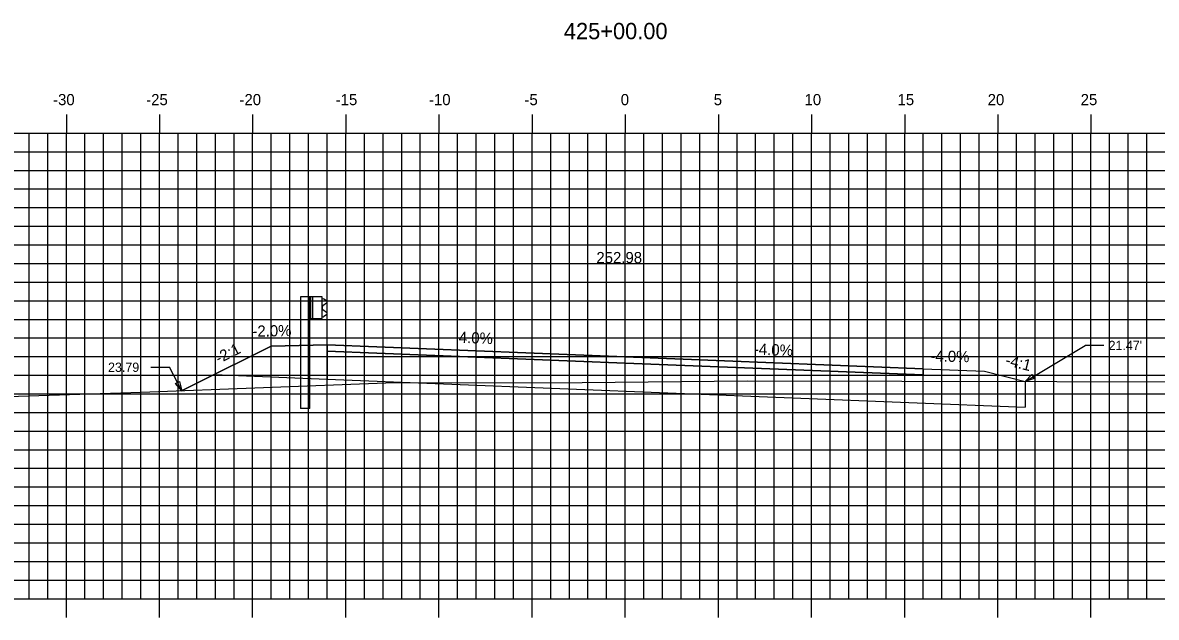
# Model space of a CAD drawing. Extents: x 1160718 to 1173142, y 616002 to 617630.
# Drawn here: x 1170373.6 to 1170434.4, y 616656.9 to 616688.9 of the extents above; entities that cross this region are included whole.
import ezdxf

# ---------------------------------------------------------------- set-up
doc = ezdxf.new("R2010")
doc.units = 0
for name, color, linetype in [('ANNOTATION', 7, 'Continuous'), ('D_Guardrail_Beam_Lt', 7, 'Continuous'), ('D_Roadway_Centerline', 7, 'Continuous'), ('D_Roadway_Centerline_Text', 7, 'Continuous'), ('D_Roadway_Edge_Shoulder', 7, 'Continuous'), ('D_Roadway_Edge_TW', 7, 'Continuous'), ('D_Roadway_Pavement', 7, 'Continuous'), ('D_Roadway_SlopeLines', 7, 'Continuous'), ('D_Roadway_SubGrade', 7, 'Continuous'), ('H_V ANNOTATION', 7, 'Continuous'), ('MAJOR', 7, 'Continuous'), ('MINOR', 7, 'Continuous'), ('S_Roadway_Centerline', 7, 'Continuous'), ('SHADING', 7, 'Continuous')]:
    doc.layers.add(name, color=color, linetype=linetype)

msp = doc.modelspace()

# ---------------------------------------------------------------- linework, layer by layer
at = {"layer": 'ANNOTATION'}
for p, q in [((1170427.372, 616669.597), (1170430.601, 616671.525)), ((1170431.601, 616671.525), (1170430.601, 616671.525)), ((1170380.439, 616670.355), (1170381.439, 616670.355)), ((1170382.112, 616669.095), (1170381.439, 616670.355)), ((1170421.907, 616670.273), (1170425.193, 616670.142))]:
    msp.add_line(p, q, dxfattribs=at)
for points in [[(1170427.865, 616669.746), (1170427.372, 616669.597), (1170427.737, 616669.961)], [(1170381.986, 616669.595), (1170382.112, 616669.095), (1170381.766, 616669.477)]]:
    msp.add_lwpolyline(points, close=True, dxfattribs=at)
at = {"layer": 'D_Guardrail_Beam_Lt'}
for p, q in [((1170388.48, 616674.136), (1170388.48, 616668.136)), ((1170388.951, 616674.136), (1170388.48, 616674.136)), ((1170389.638, 616674.136), (1170388.951, 616674.136)), ((1170388.951, 616674.136), (1170388.951, 616672.97)), ((1170389.013, 616674.136), (1170389.013, 616672.97)), ((1170389.117, 616674.136), (1170389.117, 616672.97)), ((1170389.638, 616672.97), (1170389.638, 616674.136)), ((1170389.638, 616674.053), (1170389.712, 616674.038)), ((1170389.728, 616674.032), (1170389.872, 616673.932)), ((1170389.643, 616673.588), (1170389.643, 616673.518)), ((1170389.872, 616673.789), (1170389.676, 616673.653)), ((1170389.676, 616673.454), (1170389.872, 616673.317)), ((1170388.951, 616672.97), (1170389.638, 616672.97)), ((1170388.971, 616668.136), (1170388.971, 616672.97)), ((1170389.712, 616673.068), (1170389.638, 616673.053)), ((1170389.872, 616673.174), (1170389.728, 616673.074)), ((1170388.971, 616668.136), (1170388.48, 616668.136))]:
    msp.add_line(p, q, dxfattribs=at)
for centre, major_axis, start_param, end_param in [((1170389.704, 616673.998), (0.0417, 0), 0.959931, 1.376053), ((1170389.721, 616673.588), (-0.0789, 0), 5.323254, 6.283185), ((1170389.721, 616673.518), (-0.0789, 0), 6.283185, 7.243116), ((1170389.821, 616673.86), (0.0877, 0), 5.323254, 7.243116), ((1170389.704, 616673.108), (0.0417, 0), 4.907132, 5.323254), ((1170389.821, 616673.246), (0.0877, 0), 5.323254, 7.243116)]:
    msp.add_ellipse(centre, major_axis=major_axis, ratio=0.995501, start_param=start_param, end_param=end_param, dxfattribs=at)
at = {"layer": 'D_Roadway_Centerline'}
for points in [[(1170382.083, 616669.081), (1170382.919, 616669.499), (1170386.907, 616671.493), (1170389.907, 616671.553), (1170405.907, 616670.913), (1170421.907, 616670.273)], [(1170425.193, 616670.142), (1170427.372, 616669.597)]]:
    msp.add_lwpolyline(points, dxfattribs=at)
at = {"layer": 'D_Roadway_Edge_Shoulder'}
for points in [[(1170389.907, 616671.553), (1170389.907, 616671.22)], [(1170421.907, 616670.273), (1170421.907, 616669.94)]]:
    msp.add_lwpolyline(points, dxfattribs=at)
at = {"layer": 'D_Roadway_Edge_TW'}
msp.add_lwpolyline([(1170421.907, 616669.94), (1170421.907, 616670.273), (1170405.907, 616670.913), (1170389.907, 616671.553), (1170389.907, 616671.22), (1170405.907, 616670.58)], close=True, dxfattribs=at)
at = {"layer": 'D_Roadway_Pavement'}
msp.add_lwpolyline([(1170421.907, 616669.94), (1170421.907, 616669.94), (1170405.907, 616670.58), (1170389.907, 616671.22), (1170389.907, 616671.22), (1170405.907, 616670.58)], close=True, dxfattribs=at)
for points in [[(1170389.907, 616671.22), (1170389.907, 616671.22)], [(1170389.907, 616671.22), (1170389.907, 616671.22)], [(1170421.907, 616669.94), (1170421.907, 616669.94)], [(1170421.907, 616669.94), (1170421.907, 616669.94)]]:
    msp.add_lwpolyline(points, dxfattribs=at)
at = {"layer": 'D_Roadway_SlopeLines'}
for points in [[(1170386.907, 616671.493), (1170382.083, 616669.081)], [(1170425.193, 616670.142), (1170427.372, 616669.597)]]:
    msp.add_lwpolyline(points, dxfattribs=at)
at = {"layer": 'D_Roadway_SubGrade'}
for p, q in [((1170389.907, 616671.553), (1170386.907, 616671.493)), ((1170389.907, 616669.72), (1170389.907, 616671.553)), ((1170386.907, 616671.493), (1170382.919, 616669.499)), ((1170405.907, 616670.58), (1170389.907, 616671.22)), ((1170389.907, 616671.22), (1170389.907, 616669.72)), ((1170421.907, 616669.94), (1170405.907, 616670.58)), ((1170421.907, 616668.44), (1170421.907, 616670.273)), ((1170421.907, 616668.44), (1170421.907, 616669.94)), ((1170425.193, 616670.142), (1170427.372, 616669.597)), ((1170427.372, 616669.597), (1170427.372, 616668.221))]:
    msp.add_line(p, q, dxfattribs=at)
at = {"layer": 'MAJOR'}
for p, q in [((1170375.907, 616683.93), (1170375.907, 616682.928)), ((1170380.907, 616683.93), (1170380.907, 616682.928)), ((1170385.907, 616683.93), (1170385.907, 616682.928)), ((1170390.907, 616683.93), (1170390.907, 616682.928)), ((1170395.907, 616683.93), (1170395.907, 616682.928)), ((1170400.907, 616683.93), (1170400.907, 616682.928)), ((1170405.907, 616683.93), (1170405.907, 616682.928)), ((1170410.907, 616683.93), (1170410.907, 616682.928)), ((1170415.907, 616683.93), (1170415.907, 616682.928)), ((1170420.907, 616683.93), (1170420.907, 616682.928)), ((1170425.907, 616683.93), (1170425.907, 616682.928)), ((1170430.907, 616683.93), (1170430.907, 616682.928)), ((1170335.907, 616682.928), (1170475.907, 616682.928)), ((1170335.907, 616682.928), (1170475.907, 616682.928)), ((1170375.907, 616657.928), (1170375.907, 616682.928)), ((1170380.907, 616657.928), (1170380.907, 616682.928)), ((1170385.907, 616657.928), (1170385.907, 616682.928)), ((1170390.907, 616657.928), (1170390.907, 616682.928)), ((1170395.907, 616657.928), (1170395.907, 616682.928)), ((1170400.907, 616657.928), (1170400.907, 616682.928)), ((1170405.907, 616657.928), (1170405.907, 616682.928)), ((1170410.907, 616657.928), (1170410.907, 616682.928)), ((1170415.907, 616657.928), (1170415.907, 616682.928)), ((1170420.907, 616657.928), (1170420.907, 616682.928)), ((1170425.907, 616657.928), (1170425.907, 616682.928)), ((1170430.907, 616657.928), (1170430.907, 616682.928)), ((1170335.907, 616677.928), (1170475.907, 616677.928)), ((1170335.907, 616672.928), (1170475.907, 616672.928)), ((1170335.907, 616667.928), (1170475.907, 616667.928)), ((1170335.907, 616662.928), (1170475.907, 616662.928)), ((1170335.907, 616657.928), (1170475.907, 616657.928)), ((1170335.907, 616657.928), (1170475.907, 616657.928)), ((1170375.907, 616656.926), (1170375.907, 616657.928)), ((1170380.907, 616656.926), (1170380.907, 616657.928)), ((1170385.907, 616656.926), (1170385.907, 616657.928)), ((1170390.907, 616656.926), (1170390.907, 616657.928)), ((1170395.907, 616656.926), (1170395.907, 616657.928)), ((1170400.907, 616656.926), (1170400.907, 616657.928)), ((1170405.907, 616656.926), (1170405.907, 616657.928)), ((1170410.907, 616656.926), (1170410.907, 616657.928)), ((1170415.907, 616656.926), (1170415.907, 616657.928)), ((1170420.907, 616656.926), (1170420.907, 616657.928)), ((1170425.907, 616656.926), (1170425.907, 616657.928)), ((1170430.907, 616656.926), (1170430.907, 616657.928))]:
    msp.add_line(p, q, dxfattribs=at)
at = {"layer": 'MINOR'}
for p, q in [((1170373.907, 616657.928), (1170373.907, 616682.928)), ((1170374.907, 616657.928), (1170374.907, 616682.928)), ((1170376.907, 616657.928), (1170376.907, 616682.928)), ((1170377.907, 616657.928), (1170377.907, 616682.928)), ((1170378.907, 616657.928), (1170378.907, 616682.928)), ((1170379.907, 616657.928), (1170379.907, 616682.928)), ((1170381.907, 616657.928), (1170381.907, 616682.928)), ((1170382.907, 616657.928), (1170382.907, 616682.928)), ((1170383.907, 616657.928), (1170383.907, 616682.928)), ((1170384.907, 616657.928), (1170384.907, 616682.928)), ((1170386.907, 616657.928), (1170386.907, 616682.928)), ((1170387.907, 616657.928), (1170387.907, 616682.928)), ((1170388.907, 616657.928), (1170388.907, 616682.928)), ((1170389.907, 616657.928), (1170389.907, 616682.928)), ((1170391.907, 616657.928), (1170391.907, 616682.928)), ((1170392.907, 616657.928), (1170392.907, 616682.928)), ((1170393.907, 616657.928), (1170393.907, 616682.928)), ((1170394.907, 616657.928), (1170394.907, 616682.928)), ((1170396.907, 616657.928), (1170396.907, 616682.928)), ((1170397.907, 616657.928), (1170397.907, 616682.928)), ((1170398.907, 616657.928), (1170398.907, 616682.928)), ((1170399.907, 616657.928), (1170399.907, 616682.928)), ((1170401.907, 616657.928), (1170401.907, 616682.928)), ((1170402.907, 616657.928), (1170402.907, 616682.928)), ((1170403.907, 616657.928), (1170403.907, 616682.928)), ((1170404.907, 616657.928), (1170404.907, 616682.928)), ((1170406.907, 616657.928), (1170406.907, 616682.928)), ((1170407.907, 616657.928), (1170407.907, 616682.928)), ((1170408.907, 616657.928), (1170408.907, 616682.928)), ((1170409.907, 616657.928), (1170409.907, 616682.928)), ((1170411.907, 616657.928), (1170411.907, 616682.928)), ((1170412.907, 616657.928), (1170412.907, 616682.928)), ((1170413.907, 616657.928), (1170413.907, 616682.928)), ((1170414.907, 616657.928), (1170414.907, 616682.928)), ((1170416.907, 616657.928), (1170416.907, 616682.928)), ((1170417.907, 616657.928), (1170417.907, 616682.928)), ((1170418.907, 616657.928), (1170418.907, 616682.928)), ((1170419.907, 616657.928), (1170419.907, 616682.928)), ((1170421.907, 616657.928), (1170421.907, 616682.928)), ((1170422.907, 616657.928), (1170422.907, 616682.928)), ((1170423.907, 616657.928), (1170423.907, 616682.928)), ((1170424.907, 616657.928), (1170424.907, 616682.928)), ((1170426.907, 616657.928), (1170426.907, 616682.928)), ((1170427.907, 616657.928), (1170427.907, 616682.928)), ((1170428.907, 616657.928), (1170428.907, 616682.928)), ((1170429.907, 616657.928), (1170429.907, 616682.928)), ((1170431.907, 616657.928), (1170431.907, 616682.928)), ((1170432.907, 616657.928), (1170432.907, 616682.928)), ((1170433.907, 616657.928), (1170433.907, 616682.928)), ((1170335.907, 616681.928), (1170475.907, 616681.928)), ((1170335.907, 616680.928), (1170475.907, 616680.928)), ((1170335.907, 616679.928), (1170475.907, 616679.928)), ((1170335.907, 616678.928), (1170475.907, 616678.928)), ((1170335.907, 616676.928), (1170475.907, 616676.928)), ((1170335.907, 616675.928), (1170475.907, 616675.928)), ((1170335.907, 616674.928), (1170475.907, 616674.928)), ((1170335.907, 616673.928), (1170475.907, 616673.928)), ((1170335.907, 616671.928), (1170475.907, 616671.928)), ((1170335.907, 616670.928), (1170475.907, 616670.928)), ((1170335.907, 616669.928), (1170475.907, 616669.928)), ((1170335.907, 616668.928), (1170475.907, 616668.928)), ((1170335.907, 616666.928), (1170475.907, 616666.928)), ((1170335.907, 616665.928), (1170475.907, 616665.928)), ((1170335.907, 616664.928), (1170475.907, 616664.928)), ((1170335.907, 616663.928), (1170475.907, 616663.928)), ((1170335.907, 616661.928), (1170475.907, 616661.928)), ((1170335.907, 616660.928), (1170475.907, 616660.928)), ((1170335.907, 616659.928), (1170475.907, 616659.928)), ((1170335.907, 616658.928), (1170475.907, 616658.928))]:
    msp.add_line(p, q, dxfattribs=at)
at = {"layer": 'S_Roadway_Centerline'}
msp.add_lwpolyline([(1170335.907, 616665.294), (1170355.743, 616667.556), (1170364.533, 616668.511), (1170379.922, 616669.011), (1170393.063, 616669.517), (1170403.588, 616669.541), (1170412.449, 616669.624), (1170437.381, 616669.579), (1170441.967, 616669.453), (1170452.737, 616667.352), (1170453.676, 616667.09), (1170468.662, 616671.302), (1170468.909, 616671.375), (1170468.984, 616671.391), (1170469.014, 616671.396), (1170470.06, 616671.645), (1170470.426, 616671.73), (1170472.115, 616671.808), (1170473.234, 616671.867), (1170475.907, 616671.937)], dxfattribs=at)
at = {"layer": 'SHADING'}
msp.add_lwpolyline([(1170383.845, 616669.962), (1170389.907, 616669.72), (1170427.372, 616668.221)], dxfattribs=at)

# ---------------------------------------------------------------- texts
at = {"layer": 'ANNOTATION'}
for s, rotation, p in [('-2.0%', 1.14576, (1170385.9, 616671.99)), ('4.0%', 357.70939, (1170396.963, 616671.672)), ('-2:1', 26.56505, (1170384.085, 616670.532)), ('-4.0%', 357.70939, (1170412.803, 616671.038)), ('-4.0%', 358.85424, (1170422.282, 616670.666)), ('-4:1', 345.96376, (1170426.27, 616670.479))]:
    msp.add_text(s, height=0.6, rotation=rotation, dxfattribs=at).set_placement(p)
for s, p in [("21.47'", (1170431.851, 616671.275)), ("23.79'", (1170378.146, 616670.105))]:
    msp.add_text(s, height=0.5, dxfattribs=at).set_placement(p)
at = {"layer": 'D_Roadway_Centerline'}
for s, p in [('C', (1170405.902, 616670.913)), ('L', (1170405.907, 616670.906))]:
    msp.add_text(s, height=0.0146, dxfattribs=at).set_placement(p)
at = {"layer": 'D_Roadway_Centerline_Text'}
msp.add_text('252.98', height=0.6, dxfattribs=at).set_placement((1170404.358, 616675.945))
at = {"layer": 'H_V ANNOTATION'}
for s, height, p in [('425+00.00', 0.875, (1170402.614, 616687.971)), ('-30', 0.6, (1170375.195, 616684.428)), ('-25', 0.6, (1170380.193, 616684.428)), ('-20', 0.6, (1170385.201, 616684.428)), ('-15', 0.6, (1170390.364, 616684.428)), ('-10', 0.6, (1170395.372, 616684.428)), ('-5', 0.6, (1170400.498, 616684.428)), ('0', 0.6, (1170405.666, 616684.428)), ('5', 0.6, (1170410.658, 616684.428)), ('10', 0.6, (1170415.532, 616684.428)), ('15', 0.6, (1170420.524, 616684.428)), ('20', 0.6, (1170425.361, 616684.428)), ('25', 0.6, (1170430.353, 616684.428))]:
    msp.add_text(s, height=height, dxfattribs=at).set_placement(p)

doc.saveas('drawing.dxf')
